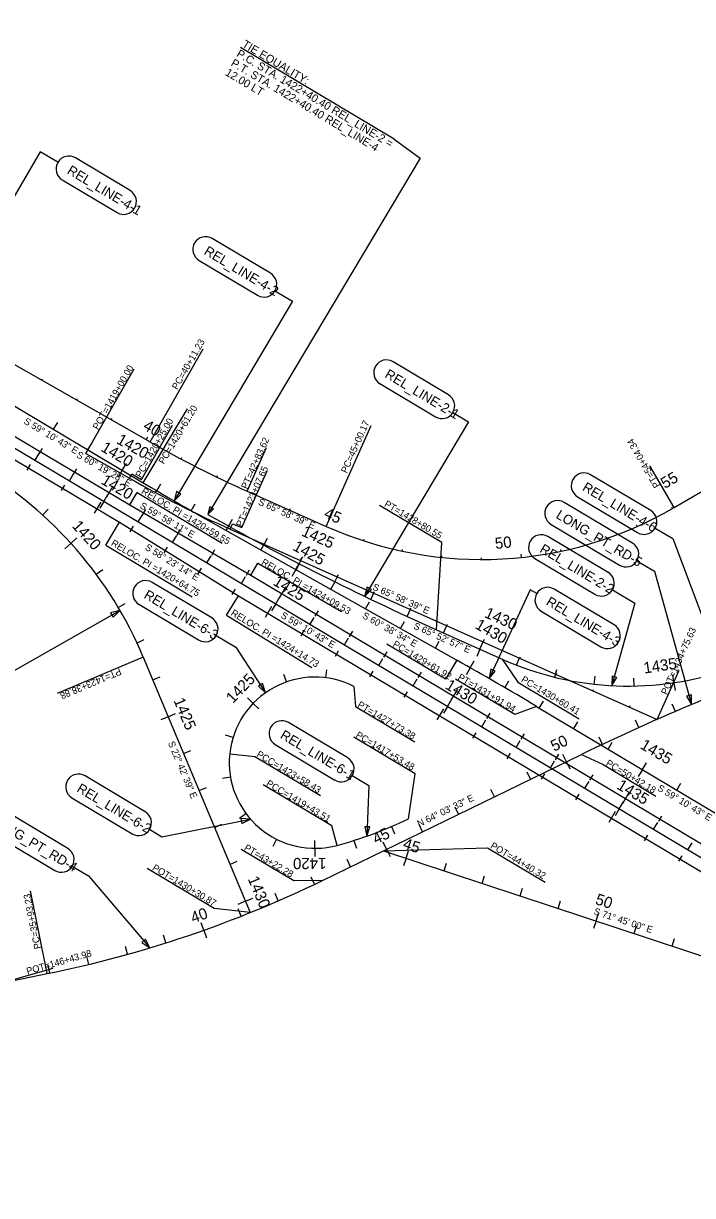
# Model space of a CAD drawing. Extents: x 2339300 to 2355400, y 360879 to 381052.
# Drawn here: x 2348046 to 2349719, y 366977 to 369907 of the extents above; entities that cross this region are included whole.
import ezdxf

# ---------------------------------------------------------------- set-up
doc = ezdxf.new("R2010")
doc.units = 0
for name, color, linetype in [('RD_HC_Cl', 7, 'Continuous'), ('RD_HC_CL_Rel', 7, 'Continuous'), ('RD_HC_Data', 7, 'Continuous'), ('RD_HC_Data_Rel', 7, 'Continuous'), ('RD_HC_Data_Tic', 7, 'Continuous'), ('RD_HC_Data_Tic_Rel', 7, 'Continuous'), ('RD_HC_TX_Rel_Sta50', 7, 'Continuous'), ('RD_HC_TX_Sta50', 7, 'Continuous'), ('RD_PD_Final_TX', 7, 'Continuous')]:
    doc.layers.add(name, color=color, linetype=linetype)

msp = doc.modelspace()

# ---------------------------------------------------------------- linework, layer by layer
at = {"layer": 'RD_HC_Cl'}
for p, q in [((2346281.6, 369885.4), (2351112.4, 367003.2)), ((2347125.2, 369566.1), (2348362.6, 368861)), ((2349672.8, 368697), (2350194.7, 369001.1)), ((2348202.5, 368832.5), (2348311.1, 368770.6)), ((2348605.5, 368738), (2348803.3, 368649.9)), ((2348563.2, 368643), (2349630, 368167.6)), ((2348794.1, 367765.1), (2349441.5, 368080)), ((2348946.1, 367839.1), (2350136.8, 367446.4)), ((2347414.1, 367392.2), (2348105.3, 367532.1))]:
    msp.add_line(p, q, dxfattribs=at)
for centre, radius, start, end in [((2349729.4, 371259.7), 2760.8, 240.3243, 245.9774), ((2349729.4, 371259.7), 2864.8, 240.3243, 245.9774), ((2349192, 369522.1), 954.9, 245.9774, 300.2274), ((2351947.8, 362927.7), 5729.6, 109.58804, 115.94073), ((2347533.9, 370355.7), 2880.8, 281.4407, 295.9407)]:
    msp.add_arc(centre, radius, start, end, dxfattribs=at)
at = {"layer": 'RD_HC_CL_Rel'}
for p, q in [((2346294.5, 369907), (2348311.8, 368703.5)), ((2346268.7, 369863.8), (2348286, 368660.2)), ((2347900.5, 369024.7), (2348345.9, 368759)), ((2348311.8, 368703.5), (2348614.8, 368528.3)), ((2348286, 368660.2), (2348584, 368476.8)), ((2348500.9, 368669.2), (2349129.8, 368315.4)), ((2348614.8, 368528.3), (2351127.8, 367029)), ((2348584, 368476.8), (2351097, 366977.5)), ((2348345.7, 368322.9), (2348612.9, 367684.6)), ((2349328.8, 368200.1), (2349833.3, 367899.1))]:
    msp.add_line(p, q, dxfattribs=at)
for centre, radius, start, end in [((2347423.3, 367936.8), 1000, 22.7108, 59.1785), ((2351938.6, 374780.7), 7012, 239.17851, 240.64281), ((2344717.5, 360471.2), 9000, 59.17851, 60.64281), ((2348774.7, 368059.3), 214, 62.9734, 174.0669), ((2348774.6, 368059.3), 214, 174.0669, 285.1604), ((2348566.5, 368827.6), 1010, 285.1604, 295.9407)]:
    msp.add_arc(centre, radius, start, end, dxfattribs=at)
at = {"layer": 'RD_HC_Data'}
for p, q in [((2348313.1, 369489.3), (2348176.1, 369571)), ((2348143.3, 369516), (2348280.3, 369434.3)), ((2348663.8, 369282.6), (2348518.1, 369369.5)), ((2348485.4, 369314.5), (2348631, 369227.6)), ((2348362.6, 368861), (2348495.1, 369093.7)), ((2348202.5, 368832.5), (2348322.9, 369043.8)), ((2349108.6, 368978.9), (2348970, 369061.6)), ((2348937.2, 369006.7), (2349075.8, 368924)), ((2348803.3, 368649.9), (2348915.8, 368902.3)), ((2348605.5, 368738), (2348654.1, 368847)), ((2348311.1, 368770.6), (2348317.4, 368781.7)), ((2349614.2, 368689.5), (2349463.9, 368779.2)), ((2349672.8, 368697), (2349612.2, 368801)), ((2349431.1, 368724.2), (2349581.4, 368634.5)), ((2349568.6, 368608.2), (2349397.9, 368710)), ((2348563.2, 368643), (2348569.2, 368656.7)), ((2349365.1, 368655.1), (2349535.8, 368553.2)), ((2349507.5, 368535.1), (2349357.1, 368624.8)), ((2349324.4, 368569.9), (2349474.7, 368480.2)), ((2348517, 368421.1), (2348367.8, 368510.1)), ((2349522.4, 368404.1), (2349373.2, 368493.2)), ((2348335, 368455.2), (2348484.2, 368366.1)), ((2349340.4, 368438.2), (2349489.6, 368349.1)), ((2349630, 368167.6), (2349684.9, 368290.8)), ((2348857.1, 368071.1), (2348708.5, 368159.7)), ((2348675.7, 368104.8), (2348824.3, 368016.1)), ((2348350.5, 367936.6), (2348200.2, 368026.3)), ((2348167.4, 367971.4), (2348317.7, 367881.7)), ((2348157.2, 367845), (2347985.9, 367947.3)), ((2347953.1, 367892.3), (2348124.5, 367790.1)), ((2348105.3, 367532.1), (2348063.5, 367738.7)), ((2347994.6, 367509.7), (2348120.3, 367545.8))]:
    msp.add_line(p, q, dxfattribs=at)
for points in [[(2348132.2, 369559.9), (2348088.1, 369586.2), (2347796.2, 369085.9)], [(2348674.9, 369238.7), (2348718.4, 369212.8), (2348422.6, 368714)], [(2349119.7, 368935), (2349158.9, 368911.7), (2348898.8, 368475.1)], [(2348317.4, 368781.7), (2348341.6, 368767.3), (2348418.8, 368902.8)], [(2348569.2, 368656.7), (2348592.2, 368646.8), (2348655.6, 368789.2)], [(2349625.3, 368645.6), (2349669.2, 368619.5), (2349833.4, 368183.8)], [(2349579.6, 368564.3), (2349623.3, 368538.3), (2349716.1, 368204.8)], [(2349329.3, 368482.1), (2349313.2, 368491.7), (2349210.1, 368269.7)], [(2349518.6, 368491.3), (2349574.7, 368457.8), (2349517.1, 368251.9)], [(2347952.5, 368293), (2347989.6, 368270.9), (2348287.4, 368440)], [(2348528.1, 368377.2), (2348577, 368348), (2348651.5, 368234.3)], [(2349441.5, 368080), (2349495.2, 368054.7), (2349627.1, 367975.9)], [(2348868.2, 368027.2), (2348909.6, 368002.5), (2348904.5, 367875.9)], [(2348361.6, 367892.8), (2348392.5, 367874.3), (2348613.9, 367918)], [(2348794.1, 367765.1), (2348722, 367763.7), (2348590.3, 367842.3)], [(2348946.1, 367839.1), (2349206.4, 367846.9), (2349350.1, 367761.1)], [(2348168.3, 367801.1), (2348208.9, 367776.9), (2348361.9, 367596.4)]]:
    msp.add_lwpolyline(points, dxfattribs=at)
for points in [[(2348429.1, 368737.1), (2348422.6, 368714), (2348439.8, 368730.7)], [(2348905.3, 368498.2), (2348898.8, 368475.1), (2348916, 368491.9)], [(2348270.3, 368423.2), (2348287.4, 368440), (2348264.2, 368434)], [(2349214.3, 368293.3), (2349210.1, 368269.7), (2349225.5, 368288.1)], [(2348633.6, 368250.3), (2348651.5, 368234.3), (2348644, 368257.1)], [(2349517.4, 368275.9), (2349517.1, 368251.9), (2349529.4, 368272.6)], [(2349703.9, 368225.5), (2349716.1, 368204.8), (2349715.8, 368228.8)], [(2348592.4, 367907.4), (2348613.9, 367918), (2348590, 367919.6)], [(2348899.3, 367899.3), (2348904.5, 367875.9), (2348911.7, 367898.8)], [(2348342.2, 367610.1), (2348361.9, 367596.4), (2348351.6, 367618.1)]]:
    msp.add_lwpolyline(points, close=True, dxfattribs=at)
for centre, start, end in [((2348159.7, 369543.5), 59.1784, 239.1784), ((2348296.7, 369461.8), 239.1784, 59.1784), ((2348501.7, 369342), 59.1784, 239.1784), ((2348647.4, 369255.1), 239.1784, 59.1784), ((2348953.6, 369034.1), 59.1784, 239.1784), ((2349092.2, 368951.4), 239.1784, 59.1784), ((2349447.5, 368751.7), 59.1784, 239.1784), ((2349381.5, 368682.5), 59.1784, 239.1784), ((2349597.8, 368662), 239.1784, 59.1784), ((2349340.8, 368597.3), 59.1784, 239.1784), ((2349552.2, 368580.7), 239.1784, 59.1784), ((2348351.4, 368482.6), 59.1784, 239.1784), ((2349491.1, 368507.7), 239.1784, 59.1784), ((2349356.8, 368465.7), 59.1784, 239.1784), ((2348500.6, 368393.6), 239.1784, 59.1784), ((2349506, 368376.6), 239.1784, 59.1784), ((2348692.1, 368132.3), 59.1784, 239.1784), ((2348840.7, 368043.6), 239.1784, 59.1784), ((2348183.8, 367998.9), 59.1784, 239.1784), ((2348334.1, 367909.2), 239.1784, 59.1784), ((2348140.8, 367817.5), 239.1784, 59.1784)]:
    msp.add_arc(centre, 32, start, end, dxfattribs=at)
at = {"layer": 'RD_HC_Data_Rel'}
for p, q in [((2348345.9, 368759), (2348456.2, 368943.9)), ((2348311.8, 368703.5), (2348330.3, 368734.4)), ((2348330.3, 368734.4), (2348542.7, 368607.7)), ((2348251.9, 368603), (2348286, 368660.2)), ((2348251.9, 368603), (2348468.1, 368474)), ((2348614.8, 368528.3), (2348632.1, 368558.2)), ((2348632.1, 368558.2), (2348841.6, 368437.1)), ((2348554, 368428), (2348584, 368476.8)), ((2348554, 368428), (2348766.9, 368297)), ((2349078.3, 368391.7), (2349242.5, 368318.2)), ((2348345.7, 368322.9), (2348130.2, 368232.7))]:
    msp.add_line(p, q, dxfattribs=at)
for points in [[(2349078.3, 368391.7), (2349092.2, 368609.6), (2348936.3, 368702.6)], [(2349129.8, 368315.4), (2349100.8, 368268.3), (2348954.5, 368355.8)], [(2349242.5, 368318.2), (2349281.7, 368261), (2349435.5, 368169.3)], [(2348871.9, 368249.9), (2348876.3, 368199.8), (2349024.8, 368111.2)], [(2349328.8, 368200.1), (2349274.1, 368180.2), (2349126.3, 368268.3)], [(2349008.3, 367919.4), (2349025.5, 368031.8), (2348871.9, 368123.5)], [(2348561.8, 368081.4), (2348624.8, 368074.7), (2348788.5, 367977.1)], [(2348830.6, 367852.7), (2348817.4, 367901.4), (2348645.8, 368003.8)], [(2348612.9, 367684.6), (2348523.3, 367694.9), (2348355.9, 367794.8)]]:
    msp.add_lwpolyline(points, dxfattribs=at)
for centre, radius, start, end in [((2351938.6, 374780.7), 7000, 240.64281, 245.88247), ((2349557.9, 369022.8), 772, 245.8825, 289.588)]:
    msp.add_arc(centre, radius, start, end, dxfattribs=at)
at = {"layer": 'RD_HC_Data_Tic'}
for p, q in [((2348092.2, 369015.1), (2348094.1, 369018.6)), ((2348179, 368965.6), (2348181, 368969.1)), ((2348265.9, 368916.1), (2348267.9, 368919.5)), ((2348352.8, 368866.6), (2348356.8, 368873.5)), ((2348202.5, 368832.5), (2348204.5, 368836)), ((2348075.6, 368815.1), (2348085.9, 368832.2)), ((2348440.4, 368818.3), (2348442.2, 368821.8)), ((2348161.5, 368763.8), (2348171.7, 368781)), ((2348289.4, 368783), (2348293.3, 368790)), ((2348529.6, 368773.2), (2348531.4, 368776.8)), ((2348247.4, 368712.6), (2348257.6, 368729.8)), ((2348376.7, 368734.4), (2348378.6, 368737.9)), ((2348620.5, 368731.4), (2348622.1, 368735)), ((2348247.4, 368712.6), (2348237.1, 368695.4)), ((2348465.7, 368688.7), (2348467.4, 368692.3)), ((2348711.8, 368690.6), (2348713.4, 368694.3)), ((2349669, 368694.8), (2349667, 368698.3)), ((2348333.2, 368661.4), (2348343.5, 368678.5)), ((2348556.2, 368646.2), (2348557.8, 368649.8)), ((2348803.1, 368649.9), (2348806.4, 368657.2)), ((2349579.9, 368649.5), (2349578.3, 368653.1)), ((2348419.1, 368610.1), (2348429.4, 368627.3)), ((2348647.5, 368605.4), (2348649.1, 368609.1)), ((2348896.4, 368614.1), (2348897.7, 368617.9)), ((2349486.6, 368613.7), (2349485.4, 368617.5)), ((2348505, 368558.9), (2348515.2, 368576.1)), ((2348738.8, 368564.7), (2348742.1, 368572)), ((2348993, 368588.1), (2348993.8, 368592.1)), ((2349091.7, 368572.4), (2349092.1, 368576.4)), ((2349191.5, 368567.2), (2349191.5, 368571.2)), ((2349291.3, 368572.3), (2349290.5, 368580.3)), ((2349390, 368587.9), (2349389.2, 368591.8)), ((2348590.9, 368507.6), (2348601.1, 368524.8)), ((2348830.2, 368524), (2348831.8, 368527.7)), ((2348921.5, 368483.3), (2348923.1, 368487)), ((2348676.7, 368456.4), (2348666.5, 368439.2)), ((2348676.7, 368456.4), (2348687, 368473.6)), ((2349012.9, 368442.6), (2349014.5, 368446.3)), ((2348762.6, 368405.2), (2348772.9, 368422.3)), ((2349104.2, 368401.9), (2349105.8, 368405.5)), ((2348848.5, 368353.9), (2348858.7, 368371.1)), ((2349195.5, 368361.2), (2349198.8, 368368.5)), ((2348934.4, 368302.7), (2348944.6, 368319.9)), ((2349286.9, 368320.5), (2349288.5, 368324.1)), ((2349378.2, 368279.8), (2349379.8, 368283.4)), ((2349020.2, 368251.5), (2349030.5, 368268.6)), ((2349469.6, 368239.1), (2349471.2, 368242.7)), ((2349106.1, 368200.2), (2349095.9, 368183)), ((2349106.1, 368200.2), (2349116.4, 368217.4)), ((2349560.9, 368198.3), (2349562.5, 368202)), ((2349675.8, 368187.6), (2349667.8, 368205.9)), ((2349192, 368149), (2349202.2, 368166.2)), ((2349584.3, 368147.1), (2349576.1, 368165.3)), ((2349277.9, 368097.7), (2349288.1, 368114.9)), ((2349493.6, 368105.1), (2349485, 368123.2)), ((2349403.5, 368061.6), (2349394.8, 368079.6)), ((2349363.8, 368046.5), (2349374, 368063.7)), ((2349403.5, 368061.6), (2349412.3, 368043.6)), ((2349313.6, 368017.9), (2349304.9, 368035.8)), ((2349223.7, 367974.1), (2349214.9, 367992.1)), ((2349449.6, 367995.3), (2349459.9, 368012.5)), ((2349535.5, 367944), (2349545.8, 367961.2)), ((2349133.8, 367930.4), (2349125, 367948.3)), ((2349535.5, 367944), (2349525.3, 367926.9)), ((2349043.8, 367886.6), (2349035.1, 367904.6)), ((2349621.4, 367892.8), (2349631.6, 367910)), ((2348953.9, 367842.9), (2348945.2, 367860.9)), ((2348953.9, 367842.9), (2348962.7, 367824.9)), ((2349002.8, 367820.4), (2349009, 367839.4)), ((2349707.3, 367841.6), (2349717.5, 367858.7)), ((2348864, 367799.1), (2348855.2, 367817.1)), ((2349002.8, 367820.4), (2348996.5, 367801.4)), ((2349097.7, 367789.1), (2349104, 367808)), ((2348774, 367755.5), (2348765.4, 367773.5)), ((2349192.7, 367757.7), (2349199, 367776.7)), ((2348683, 367714), (2348675.1, 367732.3)), ((2349287.7, 367726.4), (2349293.9, 367745.4)), ((2348590.7, 367675.7), (2348583.3, 367694.3)), ((2349382.6, 367695.1), (2349388.9, 367714.1)), ((2349477.6, 367663.8), (2349471.3, 367644.8)), ((2349477.6, 367663.8), (2349483.9, 367682.8)), ((2348497, 367640.6), (2348490.3, 367659.5)), ((2348497, 367640.6), (2348503.7, 367621.8)), ((2349572.6, 367632.5), (2349578.8, 367651.5)), ((2348402.2, 367608.9), (2348396.2, 367627.9)), ((2349667.5, 367601.2), (2349673.8, 367620.1)), ((2348306.4, 367580.4), (2348301, 367599.6)), ((2348112, 367533.5), (2348108, 367553.1)), ((2348209.6, 367555.2), (2348204.9, 367574.7))]:
    msp.add_line(p, q, dxfattribs=at)
at = {"layer": 'RD_HC_Data_Tic_Rel'}
for p, q in [((2348121.6, 368892.8), (2348131.8, 368910)), ((2348085.8, 368831.3), (2348094, 368845)), ((2348207.4, 368841.6), (2348217.7, 368858.8)), ((2348293.3, 368790.4), (2348303.6, 368807.5)), ((2348055.6, 368790.7), (2348063.8, 368804.5)), ((2348171.7, 368780.1), (2348179.9, 368793.8)), ((2348293.3, 368790.4), (2348283.1, 368773.2)), ((2348141.4, 368739.5), (2348149.6, 368753.2)), ((2348254.5, 368723.7), (2348270.9, 368751.1)), ((2348379.3, 368739.2), (2348389.4, 368756.4)), ((2348094.3, 368678.3), (2348107.7, 368693.1)), ((2348224.2, 368683.1), (2348240.6, 368710.6)), ((2348343.8, 368678), (2348351.8, 368691.9)), ((2348465.8, 368689.1), (2348475.7, 368706.4)), ((2348558.9, 368650.6), (2348568.5, 368668.1)), ((2348312.9, 368636.6), (2348321.2, 368650.3)), ((2348430.4, 368628), (2348438.4, 368641.8)), ((2348552.9, 368639.9), (2348562.7, 368657.4)), ((2348164.9, 368607.6), (2348150.1, 368594.2)), ((2348164.9, 368607.6), (2348179.8, 368621)), ((2348640, 368590.9), (2348649.8, 368608.3)), ((2348646.8, 368603), (2348656.2, 368620.6)), ((2348398, 368584.2), (2348406.4, 368597.9)), ((2348516.9, 368577.9), (2348524.9, 368591.8)), ((2348735.4, 368556.6), (2348744.5, 368574.4)), ((2348228.2, 368530.2), (2348244.3, 368542.1)), ((2348483.2, 368531.8), (2348491.6, 368545.4)), ((2348603.5, 368527.9), (2348611.5, 368541.7)), ((2348727.2, 368541.9), (2348717.4, 368524.5)), ((2348735.4, 368556.6), (2348726.2, 368538.8)), ((2348727.2, 368541.9), (2348737, 368559.3)), ((2348824.6, 368511.4), (2348833.5, 368529.4)), ((2348568.3, 368479.4), (2348576.7, 368493)), ((2348686.3, 368471.7), (2348702.7, 368499.1)), ((2348814.3, 368492.9), (2348824.2, 368510.3)), ((2348914.5, 368467.6), (2348923.1, 368485.6)), ((2348283.4, 368446.9), (2348300.6, 368457.1)), ((2348901.5, 368443.8), (2348911.3, 368461.3)), ((2348651.1, 368422.8), (2348667.5, 368450.3)), ((2348775.3, 368425.6), (2348783.5, 368439.3)), ((2349005, 368425), (2349013.4, 368443.2)), ((2348988.7, 368394.8), (2348998.5, 368412.2)), ((2349096.1, 368383.8), (2349104.2, 368402)), ((2348330, 368358.5), (2348348.2, 368366.9)), ((2348740.1, 368376.7), (2348748.3, 368390.4)), ((2348861.1, 368374.3), (2348869.3, 368388.1)), ((2348825.9, 368325.5), (2348834.1, 368339.2)), ((2348947, 368323.1), (2348955.2, 368336.8)), ((2349075.8, 368345.8), (2349085.6, 368363.2)), ((2349187.3, 368342.9), (2349179.2, 368324.6)), ((2349187.3, 368342.9), (2349195.5, 368361.2)), ((2349162.9, 368296.7), (2349172.8, 368314.1)), ((2349279, 368303), (2349286.2, 368321.6)), ((2348703.6, 368261.2), (2348696.9, 368280)), ((2348802.1, 368271.5), (2348804.7, 368291.4)), ((2348911.8, 368274.2), (2348920, 368288)), ((2349032.9, 368271.9), (2349041.1, 368285.6)), ((2349162.9, 368296.7), (2349153.1, 368279.3)), ((2349374.3, 368273), (2349379.1, 368292.4)), ((2349672.1, 368259.3), (2349669.2, 368279.1)), ((2348369.3, 368266.5), (2348387.8, 368274.3)), ((2349249.6, 368246.8), (2349259.7, 368264.1)), ((2349472.7, 368255.5), (2349474.9, 368275.4)), ((2349572.6, 368251), (2349572.2, 368271)), ((2349672.1, 368259.3), (2349675.1, 368239.5)), ((2348620.3, 368207.5), (2348605.9, 368221.4)), ((2348997.7, 368223), (2349005.9, 368236.7)), ((2349115.7, 368215.5), (2349132.1, 368243)), ((2348620.3, 368207.5), (2348634.7, 368193.7)), ((2349080.5, 368166.6), (2349096.9, 368194.1)), ((2349335.7, 368196), (2349346, 368213.2)), ((2348407.9, 368174.3), (2348389.5, 368166.6)), ((2348407.9, 368174.3), (2348426.4, 368182)), ((2349204.7, 368169.4), (2349212.8, 368183.1)), ((2349421.6, 368144.7), (2349431.9, 368161.9)), ((2349169.4, 368120.5), (2349177.6, 368134.3)), ((2349290.5, 368118.1), (2349298.7, 368131.9)), ((2348570.1, 368122.1), (2348550.9, 368128)), ((2349507.5, 368093.5), (2349517.7, 368110.7)), ((2348446.6, 368082), (2348465, 368089.8)), ((2349255.3, 368069.3), (2349263.5, 368083)), ((2349376.4, 368066.9), (2349384.6, 368080.7)), ((2349593.4, 368042.3), (2349603.6, 368059.4)), ((2348563.7, 368023.2), (2348544, 368019.8)), ((2349341.2, 368018), (2349349.4, 368031.8)), ((2349462.3, 368015.7), (2349470.5, 368029.4)), ((2349593.4, 368042.3), (2349583.1, 368025.1)), ((2348485.2, 367989.8), (2348503.6, 367997.5)), ((2349545.1, 367959.3), (2349561.5, 367986.8)), ((2349679.2, 367991), (2349689.5, 368008.2)), ((2349427.1, 367966.8), (2349435.3, 367980.6)), ((2348602.6, 367932), (2348586.5, 367920.2)), ((2349509.9, 367910.4), (2349526.3, 367937.9)), ((2349634, 367913.2), (2349642.2, 367926.9)), ((2348523.8, 367897.6), (2348542.2, 367905.3)), ((2348966, 367900), (2348973.9, 367881.6)), ((2348678.4, 367868.2), (2348669.4, 367850.3)), ((2349598.8, 367864.3), (2349607, 367878.1)), ((2348774.8, 367845.3), (2348774.8, 367865.3)), ((2348774.8, 367845.3), (2348774.8, 367825.3)), ((2348872.3, 367865), (2348878.4, 367846)), ((2348562.4, 367805.3), (2348580.8, 367813)), ((2349684.7, 367813.1), (2349692.9, 367826.8)), ((2348601, 367713.1), (2348582.5, 367705.3)), ((2348601, 367713.1), (2348619.4, 367720.8))]:
    msp.add_line(p, q, dxfattribs=at)
at = {"layer": 'RD_PD_Final_TX'}
msp.add_line((2348972.9, 369617.7), (2348588.5, 369847.1), dxfattribs=at)
msp.add_lwpolyline([(2348972.9, 369617.7), (2349037.8, 369570.4), (2348506.8, 368679.6)], dxfattribs=at)
msp.add_lwpolyline([(2348512.3, 368698.9), (2348506.8, 368679.6), (2348521.1, 368693.6)], close=True, dxfattribs=at)

# ---------------------------------------------------------------- texts
at = {"layer": 'RD_HC_Data'}
for s, height, rotation, p in [('REL_LINE-4-1', 24, 329.1784, (2348153.5, 369533.2)), ('REL_LINE-4-2', 24, 329.1784, (2348495.6, 369331.7)), ('PC=40+11.23', 17, 60.3243, (2348430.9, 368990.2)), ('POT=1419+00.00', 17, 60.3243, (2348232.9, 368890)), ('REL_LINE-2-1', 24, 329.1784, (2348947.5, 369023.8)), ('PC=1420+25.00', 17, 60.3243, (2348339.9, 368770.2)), ('PC=45+00.17', 17, 65.9774, (2348854.5, 368781.6)), ('PT=42+83.62', 17, 65.9774, (2348605.1, 368741.8)), ('PT=54+04.34', 17, 120.2274, (2349638.3, 368752.1)), ('S 60%%d 19\' 28" E', 17, 330.3243, (2348177.1, 368824)), ('PT=1423+07.65', 17, 65.9774, (2348592.2, 368646.8)), ('REL_LINE-4-6', 24, 329.1784, (2349441.4, 368741.4)), ('S 65%%d 58\' 39" E', 17, 335.9774, (2348631.5, 368705.1)), ('LONG_PT_RD-5', 24, 329.1784, (2349375.3, 368672.2)), ('REL_LINE-2-2', 24, 329.1784, (2349334.6, 368587)), ('REL_LINE-6-3', 24, 329.1784, (2348345.2, 368472.3)), ('S 65%%d 58\' 39" E', 17, 335.9774, (2348917.2, 368492.4)), ('REL_LINE-4-3', 24, 329.1784, (2349350.6, 368455.4)), ('S 59%%d 10\' 43" E', 17, 329.1785, (2348687.8, 368423)), ('POT=1434+75.63', 17, 65.9774, (2349654.6, 368227.7)), ('REL_LINE-6-1', 24, 329.1784, (2348686, 368122)), ('PC=50+42.18', 17, 329.1784, (2349500.4, 368053.6)), ('REL_LINE-6-2', 24, 329.1784, (2348177.6, 367988.5)), ('N 64%%d 03\' 33" E', 17, 25.9407, (2349035.4, 367898.1)), ('LONG_PT_RD-4', 24, 329.1784, (2347963.3, 367909.5)), ('PT=43+22.28', 17, 329.1784, (2348596.2, 367842.1)), ('POT=44+40.32', 17, 329.1784, (2349211.9, 367847.1)), ('PC=35+93.23', 17, 101.4407, (2348090.5, 367595.4)), ('S 71%%d 45\' 00" E', 17, 341.7499, (2349470.6, 367680.8)), ('POT=146+43.98', 17, 16.0174, (2348056.5, 367529.6))]:
    msp.add_text(s, height=height, rotation=rotation, dxfattribs=at).set_placement(p)
at = {"layer": 'RD_HC_Data_Rel'}
for s, rotation, p in [('PC=1420+61.20', 59.1785, (2348397.3, 368804)), ('S 59%%d 10\' 43" E', 329.1785, (2348045.6, 368908.1)), ('RELOC. PI =1420+59.55', 329.1785, (2348339.6, 368733.2)), ('S 59%%d 58\' 11" E', 329.9698, (2348335.8, 368696.8)), ('PT=1428+80.55', 329.1784, (2348946.6, 368701.4)), ('RELOC. PI =1420+64.75', 329.1785, (2348263.8, 368603.5)), ('S 58%%d 23\' 14" E', 328.3872, (2348348.6, 368593.2)), ('RELOC. PI =1424+09.53', 329.9698, (2348639.3, 368555.7)), ('RELOC. PI =1424+14.73', 328.3872, (2348563.2, 368429.2)), ('S 60%%d 38\' 34" E', 330.6428, (2348891.7, 368422.1)), ('S 65%%d 52\' 57" E', 335.8825, (2349019.7, 368395.1)), ('PC=1429+61.92', 329.1784, (2348967.8, 368351)), ('PT=1423+38.88', 202.7108, (2348286.5, 368296)), ('PT=1431+91.94', 329.1784, (2349130.2, 368268.2)), ('PC=1430+60.41', 329.1784, (2349288.7, 368262.7)), ('PT=1427+73.38', 329.1784, (2348879.6, 368199.8)), ('PC=1417+53.48', 329.1784, (2348875.4, 368124)), ('S 22%%d 42\' 39" E', 292.7108, (2348407, 368108.9)), ('PCC=1423+58.43', 329.1358, (2348627.3, 368075.7)), ('PCC=1419+43.51', 329.1784, (2348651.6, 368002.9)), ('S 59%%d 10\' 43" E', 329.1785, (2349629.3, 367991.2)), ('POT=1430+30.87', 329.1784, (2348366.7, 367792))]:
    msp.add_text(s, height=17, rotation=rotation, dxfattribs=at).set_placement(p)
at = {"layer": 'RD_HC_TX_Rel_Sta50'}
for s, rotation, p in [('1420', 329.1785, (2348237.7, 368839.9)), ('1420', 312.1269, (2348166.2, 368649.8)), ('1425', 330.6428, (2348717.4, 368592.3)), ('1430', 330.4004, (2349172.9, 368396.4)), ('1435', 8.5078, (2349598.3, 368282.1)), ('1425', 46.1654, (2348569.7, 368205.8)), ('1425', 292.7108, (2348421, 368215)), ('1435', 329.1785, (2349585.6, 368096.4)), ('1420', 180.0365, (2348803.4, 367821.4)), ('1430', 292.7108, (2348606.6, 367769.1))]:
    msp.add_text(s, height=28, rotation=rotation, dxfattribs=at).set_placement(p)
at = {"layer": 'RD_HC_TX_Sta50'}
for s, rotation, p in [('40', 330.3243, (2348343.1, 368894)), ('1420', 330.3243, (2348276.8, 368858.9)), ('1420', 329.1785, (2348238, 368758.1)), ('55', 30.2274, (2349649.5, 368743.2)), ('45', 335.9774, (2348795.2, 368673)), ('1425', 335.9774, (2348739, 368627.8)), ('50', 5.9669, (2349226.2, 368593.4)), ('1425', 329.1785, (2348667.9, 368505.2)), ('1430', 335.9774, (2349196.4, 368423.9)), ('1430', 329.1785, (2349098.4, 368246)), ('50', 25.9407, (2349372.5, 368086.7)), ('1435', 329.1785, (2349527.3, 367995.7)), ('45', 25.9407, (2348927.4, 367855)), ('45', 341.7499, (2348992.7, 367845.6)), ('50', 341.7499, (2349473.6, 367706.6)), ('40', 19.5309, (2348470.2, 367657.8))]:
    msp.add_text(s, height=28, rotation=rotation, dxfattribs=at).set_placement(p)
at = {"layer": 'RD_PD_Final_TX'}
for s, p in [('TIE EQUALITY:', (2348591.2, 369849.8)), ('P.C. STA. 1422+40.40 REL_LINE-2 =', (2348577.1, 369826.2)), ('P.T. STA. 1422+40.40 REL_LINE-4', (2348563, 369802.6)), ('12.00 LT', (2348548.9, 369779))]:
    msp.add_text(s, height=20, rotation=329.1784, dxfattribs=at).set_placement(p)

doc.saveas('drawing.dxf')
